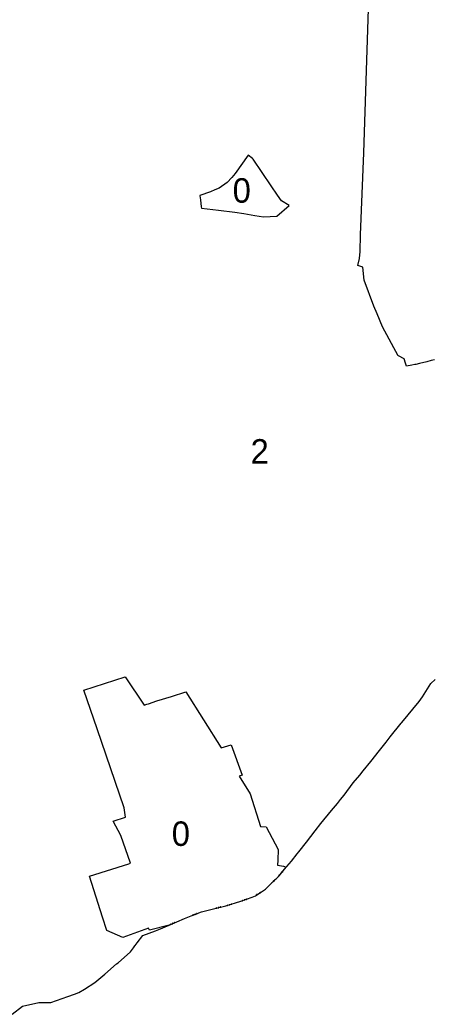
# Model space of a CAD drawing. Extents: x -609574 to -606486, y -1122348 to -1119691.
# Drawn here: x -607935 to -607430, y -1122155 to -1120937 of the extents above; entities that cross this region are included whole.
import ezdxf

# ---------------------------------------------------------------- set-up
doc = ezdxf.new("R2010")
doc.units = 0
for name, color, linetype in [('HRA_OB', 7, 'Continuous'), ('OVNE_SET', 7, 'Continuous'), ('OVNI_SET', 7, 'Continuous'), ('POZN', 7, 'Continuous')]:
    doc.layers.add(name, color=color, linetype=linetype)

msp = doc.modelspace()

# ---------------------------------------------------------------- linework, layer by layer
at = {"layer": 'HRA_OB'}
for points in [[(-607751.8, -1122045.7), (-607732.9, -1122037.6), (-607724.6, -1122034.3), (-607712.1, -1122029.7), (-607703.8, -1122027.6), (-607695.8, -1122025.5), (-607682.1, -1122022.2), (-607663.8, -1122016.6), (-607649.8, -1122011.6), (-607646.1, -1122009.8), (-607633.6, -1122001.8), (-607626.7, -1121995), (-607617.9, -1121986.1), (-607608.2, -1121974.9)], [(-607616.6, -1121984.2), (-607616.4, -1121984.1), (-607616.1, -1121984.3), (-607616.1, -1121984.6), (-607616.3, -1121984.8), (-607616.6, -1121984.8), (-607616.8, -1121984.6), (-607616.8, -1121984.4), (-607616.6, -1121984.2), (-607616.6, -1121984.2), (-607616.7, -1121984.4), (-607616.7, -1121984.5), (-607616.5, -1121984.2), (-607616.4, -1121984.2), (-607616.7, -1121984.6), (-607616.7, -1121984.6), (-607616.3, -1121984.2), (-607616.3, -1121984.3), (-607616.6, -1121984.7), (-607616.5, -1121984.7), (-607616.2, -1121984.3), (-607616.2, -1121984.4), (-607616.4, -1121984.7), (-607616.3, -1121984.7), (-607616.2, -1121984.5)], [(-607615, -1121982.3), (-607614.7, -1121982.2), (-607614.5, -1121982.4), (-607614.5, -1121982.7), (-607614.7, -1121982.9), (-607614.9, -1121982.9), (-607615.1, -1121982.7), (-607615.2, -1121982.5), (-607615, -1121982.3), (-607615, -1121982.3), (-607615.1, -1121982.5), (-607615.1, -1121982.6), (-607614.8, -1121982.3), (-607614.7, -1121982.3), (-607615.1, -1121982.7), (-607615, -1121982.7), (-607614.7, -1121982.3), (-607614.6, -1121982.4), (-607615, -1121982.8), (-607614.9, -1121982.9), (-607614.6, -1121982.4), (-607614.5, -1121982.5), (-607614.8, -1121982.8), (-607614.7, -1121982.8), (-607614.5, -1121982.7)], [(-607613.3, -1121980.4), (-607613.1, -1121980.3), (-607612.9, -1121980.5), (-607612.9, -1121980.8), (-607613, -1121981), (-607613.3, -1121981), (-607613.5, -1121980.8), (-607613.5, -1121980.6), (-607613.3, -1121980.4), (-607613.3, -1121980.4), (-607613.5, -1121980.6), (-607613.5, -1121980.7), (-607613.2, -1121980.4), (-607613.1, -1121980.4), (-607613.5, -1121980.8), (-607613.4, -1121980.8), (-607613.1, -1121980.4), (-607613, -1121980.5), (-607613.3, -1121980.9), (-607613.3, -1121981), (-607612.9, -1121980.6), (-607612.9, -1121980.6), (-607613.2, -1121981), (-607613.1, -1121981), (-607612.9, -1121980.8)], [(-607625.3, -1121993.1), (-607625.1, -1121993.1), (-607624.9, -1121993.3), (-607624.9, -1121993.6), (-607625.1, -1121993.8), (-607625.3, -1121993.8), (-607625.5, -1121993.6), (-607625.5, -1121993.3), (-607625.3, -1121993.1), (-607625.3, -1121993.1), (-607625.5, -1121993.3), (-607625.5, -1121993.4), (-607625.2, -1121993.1), (-607625.1, -1121993.2), (-607625.5, -1121993.5), (-607625.4, -1121993.6), (-607625, -1121993.2), (-607625, -1121993.3), (-607625.3, -1121993.6), (-607625.3, -1121993.7), (-607624.9, -1121993.3), (-607624.9, -1121993.4), (-607625.2, -1121993.7), (-607625.1, -1121993.7), (-607624.9, -1121993.5)], [(-607623.6, -1121991.3), (-607623.3, -1121991.3), (-607623.1, -1121991.5), (-607623.1, -1121991.8), (-607623.3, -1121992), (-607623.5, -1121992), (-607623.7, -1121991.8), (-607623.7, -1121991.5), (-607623.6, -1121991.3), (-607623.5, -1121991.4), (-607623.7, -1121991.6), (-607623.7, -1121991.7), (-607623.4, -1121991.4), (-607623.3, -1121991.4), (-607623.7, -1121991.8), (-607623.6, -1121991.8), (-607623.2, -1121991.4), (-607623.2, -1121991.5), (-607623.6, -1121991.9), (-607623.5, -1121991.9), (-607623.1, -1121991.6), (-607623.1, -1121991.7), (-607623.4, -1121991.9), (-607623.3, -1121991.9), (-607623.1, -1121991.8)], [(-607621.8, -1121989.6), (-607621.5, -1121989.6), (-607621.3, -1121989.8), (-607621.3, -1121990), (-607621.5, -1121990.2), (-607621.8, -1121990.2), (-607622, -1121990), (-607622, -1121989.8), (-607621.8, -1121989.6), (-607621.8, -1121989.6), (-607621.9, -1121989.8), (-607621.9, -1121989.9), (-607621.7, -1121989.6), (-607621.6, -1121989.6), (-607621.9, -1121990), (-607621.9, -1121990), (-607621.5, -1121989.7), (-607621.4, -1121989.7), (-607621.8, -1121990.1), (-607621.8, -1121990.2), (-607621.4, -1121989.8), (-607621.4, -1121989.9), (-607621.6, -1121990.2), (-607621.6, -1121990.2), (-607621.4, -1121990)], [(-607644.3, -1122008.3), (-607644, -1122008.3), (-607643.9, -1122008.5), (-607643.9, -1122008.8), (-607644.1, -1122009), (-607644.4, -1122008.9), (-607644.6, -1122008.7), (-607644.5, -1122008.4), (-607644.3, -1122008.3), (-607644.2, -1122008.3), (-607644.4, -1122008.4), (-607644.5, -1122008.5), (-607644.1, -1122008.3), (-607644, -1122008.3), (-607644.5, -1122008.6), (-607644.5, -1122008.7), (-607644, -1122008.4), (-607644, -1122008.5), (-607644.4, -1122008.8), (-607644.4, -1122008.8), (-607643.9, -1122008.5), (-607643.9, -1122008.6), (-607644.3, -1122008.9), (-607644.2, -1122008.9), (-607643.9, -1122008.8)], [(-607642.2, -1122006.9), (-607641.9, -1122007), (-607641.8, -1122007.2), (-607641.8, -1122007.4), (-607642, -1122007.6), (-607642.3, -1122007.5), (-607642.4, -1122007.3), (-607642.4, -1122007), (-607642.2, -1122006.9), (-607642.2, -1122006.9), (-607642.4, -1122007.1), (-607642.4, -1122007.2), (-607642, -1122007), (-607641.9, -1122007), (-607642.4, -1122007.3), (-607642.4, -1122007.4), (-607641.9, -1122007.1), (-607641.8, -1122007.1), (-607642.3, -1122007.4), (-607642.3, -1122007.5), (-607641.8, -1122007.2), (-607641.8, -1122007.3), (-607642.2, -1122007.5), (-607642, -1122007.5), (-607641.8, -1122007.4)], [(-607640.1, -1122005.5), (-607639.8, -1122005.6), (-607639.6, -1122005.8), (-607639.7, -1122006.1), (-607639.9, -1122006.2), (-607640.2, -1122006.2), (-607640.3, -1122006), (-607640.3, -1122005.7), (-607640.1, -1122005.5), (-607640.1, -1122005.6), (-607640.3, -1122005.7), (-607640.3, -1122005.8), (-607640, -1122005.6), (-607639.8, -1122005.6), (-607640.3, -1122005.9), (-607640.2, -1122006), (-607639.8, -1122005.7), (-607639.8, -1122005.8), (-607640.2, -1122006.1), (-607640.2, -1122006.1), (-607639.7, -1122005.9), (-607639.7, -1122005.9), (-607640.1, -1122006.2), (-607640, -1122006.2), (-607639.8, -1122006.1)], [(-607693.6, -1122024.7), (-607693.4, -1122024.8), (-607693.3, -1122025.1), (-607693.4, -1122025.3), (-607693.7, -1122025.4), (-607693.9, -1122025.2), (-607694, -1122025), (-607693.9, -1122024.7), (-607693.6, -1122024.7), (-607693.6, -1122024.7), (-607693.8, -1122024.8), (-607693.9, -1122024.9), (-607693.5, -1122024.8), (-607693.4, -1122024.8), (-607693.9, -1122025), (-607693.9, -1122025), (-607693.4, -1122024.9), (-607693.4, -1122025), (-607693.9, -1122025.1), (-607693.9, -1122025.2), (-607693.4, -1122025.1), (-607693.4, -1122025.1), (-607693.8, -1122025.2), (-607693.7, -1122025.3), (-607693.4, -1122025.2)], [(-607691.2, -1122024.1), (-607690.9, -1122024.2), (-607690.9, -1122024.5), (-607691, -1122024.7), (-607691.3, -1122024.8), (-607691.5, -1122024.6), (-607691.6, -1122024.4), (-607691.4, -1122024.1), (-607691.2, -1122024.1), (-607691.2, -1122024.1), (-607691.4, -1122024.2), (-607691.5, -1122024.3), (-607691.1, -1122024.2), (-607691, -1122024.2), (-607691.5, -1122024.4), (-607691.5, -1122024.4), (-607691, -1122024.3), (-607690.9, -1122024.4), (-607691.5, -1122024.5), (-607691.5, -1122024.6), (-607690.9, -1122024.5), (-607691, -1122024.6), (-607691.4, -1122024.6), (-607691.3, -1122024.7), (-607691, -1122024.6)], [(-607688.7, -1122023.5), (-607688.5, -1122023.6), (-607688.4, -1122023.9), (-607688.6, -1122024.1), (-607688.8, -1122024.2), (-607689.1, -1122024), (-607689.1, -1122023.8), (-607689, -1122023.5), (-607688.7, -1122023.5), (-607688.8, -1122023.5), (-607689, -1122023.6), (-607689, -1122023.7), (-607688.7, -1122023.6), (-607688.6, -1122023.6), (-607689.1, -1122023.8), (-607689.1, -1122023.8), (-607688.5, -1122023.7), (-607688.5, -1122023.8), (-607689, -1122023.9), (-607689, -1122024), (-607688.5, -1122023.9), (-607688.5, -1122024), (-607688.9, -1122024.1), (-607688.9, -1122024.1), (-607688.6, -1122024.1)], [(-607680, -1122021.2), (-607679.7, -1122021.3), (-607679.7, -1122021.6), (-607679.8, -1122021.8), (-607680, -1122021.9), (-607680.3, -1122021.8), (-607680.4, -1122021.5), (-607680.2, -1122021.3), (-607680, -1122021.2), (-607680, -1122021.2), (-607680.2, -1122021.3), (-607680.2, -1122021.4), (-607679.9, -1122021.3), (-607679.8, -1122021.3), (-607680.3, -1122021.5), (-607680.3, -1122021.6), (-607679.8, -1122021.4), (-607679.7, -1122021.5), (-607680.2, -1122021.6), (-607680.2, -1122021.7), (-607679.7, -1122021.6), (-607679.7, -1122021.7), (-607680.1, -1122021.8), (-607680, -1122021.8), (-607679.8, -1122021.8)], [(-607677.6, -1122020.5), (-607677.3, -1122020.6), (-607677.3, -1122020.8), (-607677.4, -1122021.1), (-607677.6, -1122021.2), (-607677.9, -1122021), (-607678, -1122020.8), (-607677.8, -1122020.5), (-607677.6, -1122020.5), (-607677.6, -1122020.5), (-607677.8, -1122020.6), (-607677.9, -1122020.7), (-607677.5, -1122020.5), (-607677.4, -1122020.6), (-607677.9, -1122020.8), (-607677.9, -1122020.8), (-607677.3, -1122020.7), (-607677.3, -1122020.8), (-607677.9, -1122020.9), (-607677.8, -1122021), (-607677.3, -1122020.8), (-607677.4, -1122020.9), (-607677.7, -1122021), (-607677.6, -1122021.1), (-607677.4, -1122021)], [(-607675.2, -1122019.7), (-607674.9, -1122019.8), (-607674.9, -1122020.1), (-607675, -1122020.3), (-607675.2, -1122020.4), (-607675.5, -1122020.3), (-607675.6, -1122020), (-607675.4, -1122019.8), (-607675.2, -1122019.7), (-607675.2, -1122019.8), (-607675.4, -1122019.8), (-607675.5, -1122019.9), (-607675.1, -1122019.8), (-607675, -1122019.9), (-607675.5, -1122020), (-607675.5, -1122020.1), (-607675, -1122020), (-607675, -1122020), (-607675.5, -1122020.2), (-607675.4, -1122020.3), (-607674.9, -1122020.1), (-607675, -1122020.2), (-607675.3, -1122020.3), (-607675.3, -1122020.4), (-607675, -1122020.3)], [(-607661.7, -1122015.5), (-607661.5, -1122015.6), (-607661.4, -1122015.9), (-607661.5, -1122016.1), (-607661.8, -1122016.2), (-607662, -1122016.1), (-607662.1, -1122015.8), (-607662, -1122015.6), (-607661.7, -1122015.5), (-607661.7, -1122015.5), (-607661.9, -1122015.6), (-607662, -1122015.7), (-607661.6, -1122015.6), (-607661.5, -1122015.6), (-607662, -1122015.8), (-607662, -1122015.9), (-607661.5, -1122015.7), (-607661.5, -1122015.8), (-607662, -1122016), (-607662, -1122016), (-607661.5, -1122015.9), (-607661.5, -1122016), (-607661.9, -1122016.1), (-607661.8, -1122016.2), (-607661.5, -1122016.1)], [(-607659.4, -1122014.7), (-607659.1, -1122014.8), (-607659, -1122015), (-607659.2, -1122015.3), (-607659.4, -1122015.4), (-607659.7, -1122015.2), (-607659.8, -1122015), (-607659.6, -1122014.7), (-607659.4, -1122014.7), (-607659.4, -1122014.7), (-607659.6, -1122014.8), (-607659.7, -1122014.9), (-607659.3, -1122014.7), (-607659.2, -1122014.8), (-607659.7, -1122015), (-607659.7, -1122015.1), (-607659.1, -1122014.9), (-607659.1, -1122014.9), (-607659.6, -1122015.1), (-607659.6, -1122015.2), (-607659.1, -1122015), (-607659.1, -1122015.1), (-607659.5, -1122015.3), (-607659.4, -1122015.3), (-607659.2, -1122015.2)], [(-607657, -1122013.8), (-607656.8, -1122013.9), (-607656.7, -1122014.2), (-607656.8, -1122014.4), (-607657.1, -1122014.5), (-607657.3, -1122014.4), (-607657.4, -1122014.1), (-607657.3, -1122013.9), (-607657, -1122013.8), (-607657, -1122013.9), (-607657.3, -1122013.9), (-607657.3, -1122014), (-607656.9, -1122013.9), (-607656.8, -1122014), (-607657.3, -1122014.1), (-607657.3, -1122014.2), (-607656.8, -1122014), (-607656.8, -1122014.1), (-607657.3, -1122014.3), (-607657.3, -1122014.4), (-607656.8, -1122014.2), (-607656.8, -1122014.3), (-607657.2, -1122014.4), (-607657.1, -1122014.5), (-607656.9, -1122014.4)], [(-607722.6, -1122033.2), (-607722.3, -1122033.3), (-607722.2, -1122033.6), (-607722.3, -1122033.8), (-607722.6, -1122033.9), (-607722.8, -1122033.8), (-607722.9, -1122033.6), (-607722.8, -1122033.3), (-607722.6, -1122033.2), (-607722.5, -1122033.3), (-607722.8, -1122033.3), (-607722.8, -1122033.5), (-607722.4, -1122033.3), (-607722.3, -1122033.4), (-607722.9, -1122033.6), (-607722.8, -1122033.6), (-607722.3, -1122033.4), (-607722.3, -1122033.5), (-607722.8, -1122033.7), (-607722.8, -1122033.8), (-607722.3, -1122033.6), (-607722.3, -1122033.7), (-607722.7, -1122033.8), (-607722.6, -1122033.9), (-607722.3, -1122033.8)], [(-607720.2, -1122032.4), (-607720, -1122032.5), (-607719.9, -1122032.7), (-607720, -1122033), (-607720.2, -1122033.1), (-607720.5, -1122033), (-607720.6, -1122032.7), (-607720.5, -1122032.5), (-607720.2, -1122032.4), (-607720.2, -1122032.4), (-607720.4, -1122032.5), (-607720.5, -1122032.6), (-607720.1, -1122032.5), (-607720, -1122032.5), (-607720.5, -1122032.7), (-607720.5, -1122032.8), (-607720, -1122032.6), (-607719.9, -1122032.6), (-607720.5, -1122032.8), (-607720.4, -1122032.9), (-607719.9, -1122032.7), (-607720, -1122032.8), (-607720.3, -1122033), (-607720.2, -1122033), (-607720, -1122032.9)], [(-607717.8, -1122031.5), (-607717.6, -1122031.6), (-607717.5, -1122031.9), (-607717.6, -1122032.1), (-607717.9, -1122032.2), (-607718.1, -1122032.1), (-607718.2, -1122031.8), (-607718.1, -1122031.6), (-607717.8, -1122031.5), (-607717.9, -1122031.5), (-607718.1, -1122031.6), (-607718.1, -1122031.7), (-607717.8, -1122031.6), (-607717.7, -1122031.6), (-607718.2, -1122031.8), (-607718.1, -1122031.9), (-607717.6, -1122031.7), (-607717.6, -1122031.8), (-607718.1, -1122032), (-607718.1, -1122032), (-607717.6, -1122031.9), (-607717.6, -1122032), (-607718, -1122032.1), (-607717.9, -1122032.2), (-607717.7, -1122032.1)], [(-607749.8, -1122044.5), (-607749.5, -1122044.6), (-607749.4, -1122044.8), (-607749.5, -1122045.1), (-607749.8, -1122045.2), (-607750, -1122045.1), (-607750.1, -1122044.8), (-607750, -1122044.6), (-607749.8, -1122044.5), (-607749.8, -1122044.5), (-607750, -1122044.6), (-607750, -1122044.7), (-607749.7, -1122044.6), (-607749.6, -1122044.6), (-607750.1, -1122044.8), (-607750, -1122044.9), (-607749.6, -1122044.7), (-607749.5, -1122044.8), (-607750, -1122045), (-607750, -1122045), (-607749.5, -1122044.8), (-607749.5, -1122044.9), (-607749.9, -1122045.1), (-607749.8, -1122045.1), (-607749.5, -1122045)], [(-607747.5, -1122043.5), (-607747.2, -1122043.6), (-607747.1, -1122043.9), (-607747.2, -1122044.1), (-607747.5, -1122044.2), (-607747.7, -1122044.1), (-607747.8, -1122043.9), (-607747.7, -1122043.6), (-607747.5, -1122043.5), (-607747.5, -1122043.5), (-607747.7, -1122043.6), (-607747.7, -1122043.7), (-607747.4, -1122043.6), (-607747.3, -1122043.6), (-607747.8, -1122043.9), (-607747.8, -1122043.9), (-607747.2, -1122043.7), (-607747.2, -1122043.8), (-607747.7, -1122044), (-607747.7, -1122044.1), (-607747.2, -1122043.9), (-607747.2, -1122044), (-607747.6, -1122044.1), (-607747.5, -1122044.2), (-607747.3, -1122044.1)], [(-607745.2, -1122042.5), (-607744.9, -1122042.6), (-607744.8, -1122042.9), (-607744.9, -1122043.1), (-607745.2, -1122043.2), (-607745.4, -1122043.1), (-607745.5, -1122042.9), (-607745.4, -1122042.6), (-607745.2, -1122042.5), (-607745.2, -1122042.6), (-607745.4, -1122042.7), (-607745.4, -1122042.8), (-607745.1, -1122042.6), (-607745, -1122042.7), (-607745.5, -1122042.9), (-607745.4, -1122042.9), (-607745, -1122042.7), (-607744.9, -1122042.8), (-607745.4, -1122043), (-607745.4, -1122043.1), (-607744.9, -1122042.9), (-607744.9, -1122043), (-607745.3, -1122043.1), (-607745.2, -1122043.2), (-607745, -1122043.1)]]:
    msp.add_lwpolyline(points, dxfattribs=at)
at = {"layer": 'OVNE_SET'}
for points in [[(-607426.8, -1121353.4), (-607430.7, -1121354.4), (-607435.9, -1121355.7), (-607444.9, -1121358.1), (-607449.4, -1121359), (-607450.8, -1121359.3), (-607454.3, -1121360), (-607461.1, -1121361.3), (-607462.2, -1121357.6), (-607463.7, -1121352.3), (-607470.9, -1121348.7), (-607471, -1121348.4), (-607490.2, -1121313), (-607497, -1121297.2), (-607501, -1121287.7), (-607512.7, -1121256), (-607514.6, -1121239.9), (-607520.5, -1121237.9), (-607518.5, -1121229.2), (-607517.5, -1121220.7), (-607517.2, -1121200.4), (-607513.3, -1121099.8), (-607510, -1120999), (-607506.7, -1120898.3)], [(-607944.1, -1122154.8), (-607931.2, -1122145.2), (-607911.2, -1122140.7), (-607896.7, -1122140.4), (-607875.8, -1122133.1), (-607867.7, -1122130.5), (-607862.4, -1122128.2), (-607855.2, -1122124.4), (-607842.8, -1122116), (-607830.6, -1122105.8), (-607816, -1122093.4), (-607814.3, -1122092), (-607798.9, -1122078.7), (-607795.4, -1122073.6), (-607793.9, -1122071.3), (-607793.5, -1122070.8), (-607790.9, -1122067.4), (-607784, -1122058.4), (-607768.3, -1122052.8), (-607764.2, -1122051.2), (-607751.8, -1122045.7), (-607775.8, -1122052.1), (-607776.8, -1122049.6), (-607808.6, -1122060.8), (-607827.9, -1122052.4), (-607833.2, -1122036), (-607838.5, -1122019.5), (-607844, -1122002.6), (-607849.3, -1121986), (-607801.1, -1121970.6), (-607799.2, -1121969.9), (-607810.8, -1121936.1), (-607820.2, -1121918.6), (-607805, -1121913.4), (-607806.8, -1121902.1), (-607840, -1121805.3), (-607856.3, -1121757.9), (-607805.4, -1121741.6), (-607782.2, -1121776.3), (-607778.9, -1121775.3), (-607776.9, -1121774.6), (-607766.7, -1121771.3), (-607748.8, -1121765.6), (-607731.3, -1121759.9), (-607687.8, -1121828.8), (-607675.6, -1121825.1), (-607662.3, -1121862), (-607666.1, -1121863.2), (-607652.5, -1121884.8), (-607639.8, -1121925.1), (-607633, -1121925.3), (-607618, -1121953), (-607618.4, -1121966.1), (-607618.8, -1121972.5), (-607611.8, -1121973.7), (-607608.2, -1121974.9), (-607607.5, -1121974.1), (-607602, -1121967.4), (-607594.8, -1121958.5), (-607592.8, -1121956), (-607583.5, -1121944), (-607572.7, -1121930.4), (-607565.7, -1121921.2), (-607552.6, -1121905.4), (-607545.6, -1121896.7), (-607541.7, -1121891.9), (-607537.2, -1121886.6), (-607526.1, -1121871.7), (-607518, -1121862.2), (-607514, -1121856.9), (-607504.6, -1121845.6), (-607494.1, -1121832), (-607485.7, -1121821.6), (-607480.9, -1121815.1), (-607467.5, -1121798.4), (-607466.8, -1121797.5), (-607445.3, -1121771.8), (-607441.5, -1121766.2), (-607431, -1121749.9), (-607425.8, -1121745.1)]]:
    msp.add_lwpolyline(points, dxfattribs=at)
at = {"layer": 'OVNI_SET'}
msp.add_lwpolyline([(-607714.1, -1121152), (-607714, -1121152.6), (-607713.2, -1121157.6), (-607712.3, -1121166), (-607712, -1121167.5), (-607691.3, -1121170.1), (-607671.4, -1121172.5), (-607660, -1121174.4), (-607646.8, -1121176.5), (-607636, -1121178.2), (-607619.6, -1121177.4), (-607604.5, -1121164.6), (-607614.2, -1121158.8), (-607618.9, -1121151.8), (-607626.6, -1121140.3), (-607648.6, -1121107.5), (-607649.6, -1121106.7), (-607654.7, -1121102.6), (-607670.9, -1121125.4), (-607674.7, -1121130.2), (-607680.8, -1121136.2), (-607690.6, -1121143), (-607695.6, -1121145.3), (-607701, -1121147.8)], close=True, dxfattribs=at)

# ---------------------------------------------------------------- texts
msp.add_text('0', height=30, dxfattribs=at).set_placement((-607673.9, -1121161))
at = {"layer": 'POZN'}
for s, p in [('2', (-607651.9, -1121480.6)), ('0', (-607748.5, -1121948.8))]:
    msp.add_text(s, height=30, dxfattribs=at).set_placement(p)

doc.saveas('drawing.dxf')
